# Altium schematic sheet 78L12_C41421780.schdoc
size 127 x 101 mm
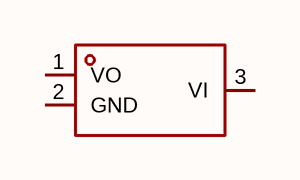
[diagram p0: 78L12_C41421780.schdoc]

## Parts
U?  78l12_c41421780  [SOT-89-3_L4.5-W2.5-P1.50-LS4.2-BR]  (value not drawn)

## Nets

Not connected (* = marked no-connect by the designer): U? 1(VO) 2(GND) 3(VI)

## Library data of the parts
U? = 78l12_c41421780: 输出极性:正极;工作电压:27V;输出电压:12V;输出电流:40mA;电源纹波抑制比(PSRR):42dB@(120Hz);输出类型:固定;; Manufacturer: JSMSEMI(杰盛微); ManufacturerPart: 78L12; AddInBom: yes; ModelId: 6db690b7897d4d18a30d90c1b89525ee; ModelName: SOT-89-3_L4.3-W2.5-H1.6-LS4.1-P1.50; ModelTransform: 161.417,169.291,0,180,0,0,-18.661,0,0; Output Configuration: 正极; Voltage - Supply: 27V; Output Voltage: 12V; Output Current: 40mA; Voltage Dropout: 1.7V@(40mA); standby current: 4.2mA; Noise: 80uV; Output Type: 固定; Number of Outputs: 1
